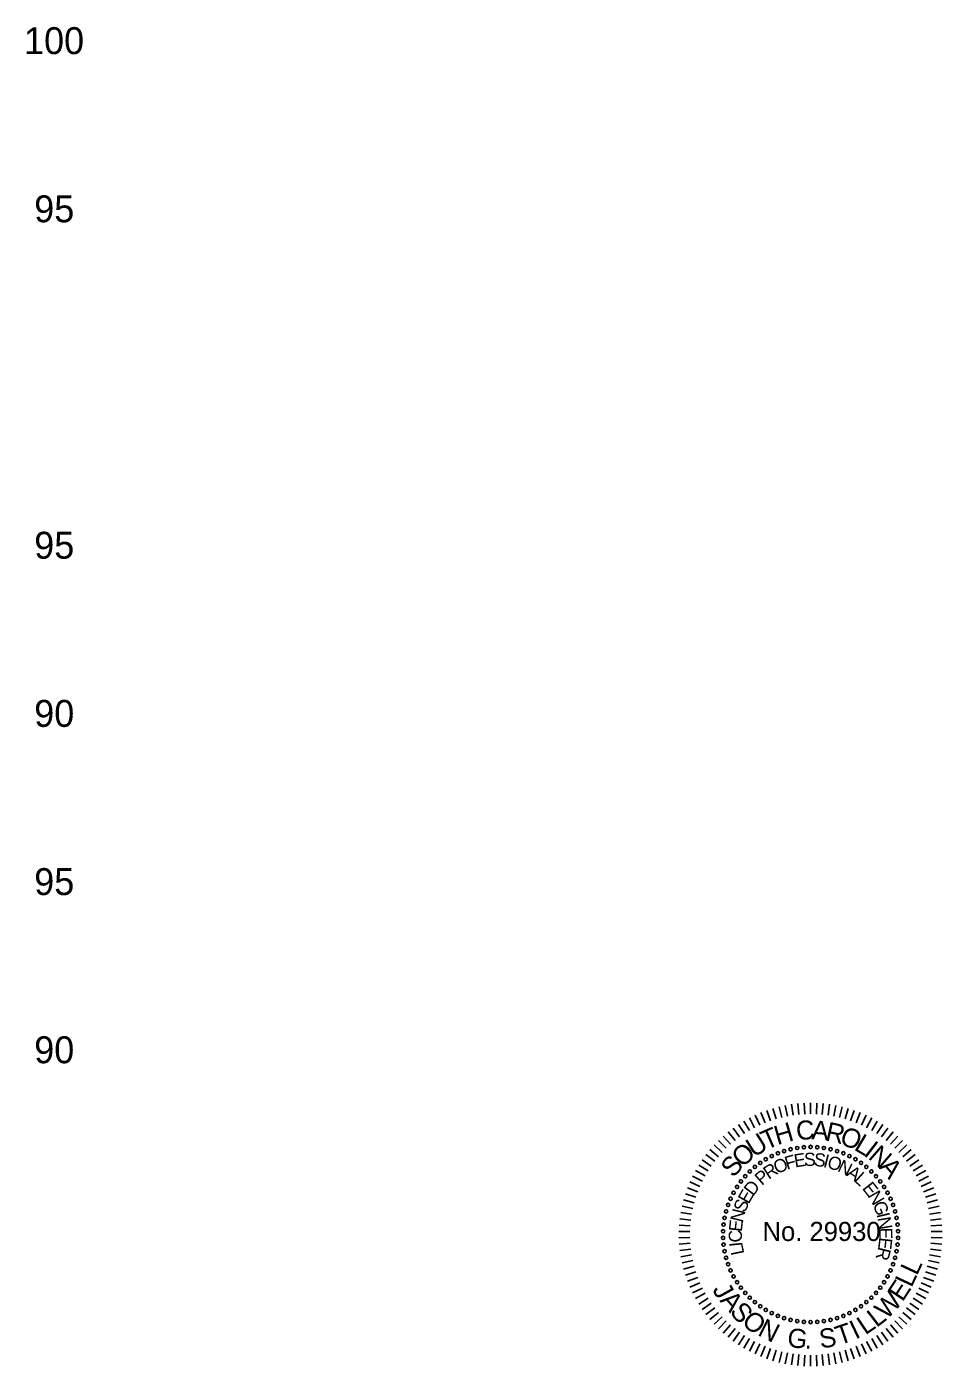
# Model space of a CAD drawing. Extents: x 1001 to 1184, y 1001 to 1102.
# Drawn here: x 1156.7 to 1183.91, y 1000.99 to 1040.81 of the extents above; entities that cross this region are included whole.
import ezdxf

# ---------------------------------------------------------------- set-up
doc = ezdxf.new("R2010")
doc.units = 0
for name, color, linetype in [('RD_HC_Cl', 7, 'Continuous'), ('RD_TX_PEShield', 7, 'Continuous'), ('RD_XS_TX_Elev_EX', 7, 'Continuous')]:
    doc.layers.add(name, color=color, linetype=linetype)

# ---------------------------------------------------------------- blocks, each defined once
blk = doc.blocks.new('STILLWELL')
at = {"layer": 'RD_TX_PEShield'}
for p, q in [((-11.93, 32.91), (-13.02, 35.99)), ((-10.28, 33.44), (-11.22, 36.57)), ((-8.61, 33.9), (-9.39, 37.07)), ((-6.92, 34.27), (-7.55, 37.48)), ((-5.21, 34.57), (-5.68, 37.8)), ((-3.49, 34.77), (-3.81, 38.03)), ((-1.76, 34.9), (-1.92, 38.16)), ((-0.03, 34.94), (-0.03, 38.21)), ((1.71, 34.9), (1.86, 38.16)), ((3.43, 34.77), (3.75, 38.03)), ((5.15, 34.57), (5.63, 37.8)), ((6.86, 34.27), (7.49, 37.48)), ((8.56, 33.9), (9.34, 37.07)), ((10.23, 33.44), (11.16, 36.57)), ((11.88, 32.91), (12.96, 35.99)), ((-18.21, 29.99), (-19.87, 32.81)), ((-16.7, 30.83), (-18.22, 33.73)), ((-15.14, 31.6), (-16.52, 34.56)), ((-13.55, 32.29), (-14.79, 35.32)), ((13.5, 32.29), (14.73, 35.32)), ((15.09, 31.6), (16.46, 34.56)), ((16.64, 30.83), (18.16, 33.73)), ((18.16, 29.99), (19.81, 32.81)), ((-23.81, 25.92), (-25.98, 28.37)), ((-22.49, 27.04), (-24.53, 29.59)), ((-21.11, 28.09), (-23.03, 30.73)), ((-19.68, 29.08), (-21.48, 31.81)), ((19.63, 29.08), (21.42, 31.81)), ((21.06, 28.09), (22.98, 30.73)), ((22.43, 27.04), (24.48, 29.59)), ((23.76, 25.92), (25.92, 28.37)), ((-27.44, 22.2), (-29.94, 24.31)), ((-26.29, 23.5), (-28.69, 25.72)), ((-25.08, 24.74), (-27.37, 27.08)), ((25.03, 24.74), (27.31, 27.08)), ((26.24, 23.5), (28.63, 25.72)), ((27.39, 22.2), (29.88, 24.31)), ((-29.55, 19.45), (-32.24, 21.3)), ((-28.53, 20.85), (-31.12, 22.83)), ((28.47, 20.85), (31.07, 22.83)), ((29.49, 19.45), (32.18, 21.3)), ((-32.18, 14.97), (-35.11, 16.42)), ((-31.38, 16.5), (-34.23, 18.09)), ((-30.5, 18), (-33.27, 19.72)), ((30.44, 18), (33.22, 19.72)), ((31.32, 16.5), (34.18, 18.09)), ((32.13, 14.97), (35.06, 16.42)), ((-33.57, 11.79), (-36.62, 12.95)), ((-32.91, 13.4), (-35.91, 14.7)), ((32.86, 13.4), (35.85, 14.7)), ((33.51, 11.79), (36.57, 12.95)), ((-34.64, 8.5), (-37.79, 9.35)), ((-34.14, 10.16), (-37.25, 11.17)), ((34.09, 10.16), (37.19, 11.17)), ((34.58, 8.5), (37.73, 9.35)), ((-35.39, 5.11), (-38.61, 5.66)), ((-35.05, 6.81), (-38.24, 7.52)), ((35, 6.81), (38.19, 7.52)), ((35.33, 5.11), (38.55, 5.66)), ((-35.89, -0.06), (-39.15, 0.02)), ((-35.8, 1.67), (-39.06, 1.91)), ((-35.64, 3.4), (-38.88, 3.79)), ((35.58, 3.4), (38.82, 3.79)), ((35.75, 1.67), (39.01, 1.91)), ((35.83, -0.06), (39.1, 0.02)), ((-35.89, -1.79), (-39.15, -1.87)), ((-35.8, -3.53), (-39.06, -3.76)), ((35.75, -3.53), (39.01, -3.76)), ((35.83, -1.79), (39.1, -1.87)), ((-35.64, -5.25), (-38.88, -5.65)), ((-35.39, -6.97), (-38.61, -7.52)), ((35.33, -6.97), (38.55, -7.52)), ((35.58, -5.25), (38.82, -5.65)), ((-35.05, -8.67), (-38.24, -9.37)), ((-34.64, -10.35), (-37.79, -11.21)), ((34.58, -10.35), (37.73, -11.21)), ((35, -8.67), (38.19, -9.37)), ((-34.14, -12.01), (-37.25, -13.02)), ((-33.57, -13.65), (-36.62, -14.81)), ((-32.91, -15.25), (-35.91, -16.56)), ((32.86, -15.25), (35.85, -16.56)), ((33.51, -13.65), (36.57, -14.81)), ((34.09, -12.01), (37.19, -13.02)), ((-32.18, -16.83), (-35.11, -18.27)), ((-31.38, -18.36), (-34.23, -19.95)), ((-30.5, -19.85), (-33.27, -21.58)), ((30.44, -19.85), (33.22, -21.58)), ((31.32, -18.36), (34.18, -19.95)), ((32.13, -16.83), (35.06, -18.27)), ((-29.55, -21.3), (-32.24, -23.16)), ((-28.53, -22.71), (-31.12, -24.69)), ((28.47, -22.71), (31.07, -24.69)), ((29.49, -21.3), (32.18, -23.16)), ((-27.44, -24.06), (-29.94, -26.16)), ((-26.29, -25.36), (-28.69, -27.58)), ((-25.08, -26.6), (-27.37, -28.93)), ((-23.81, -27.78), (-25.98, -30.22)), ((23.76, -27.78), (25.92, -30.22)), ((25.03, -26.6), (27.31, -28.93)), ((26.24, -25.36), (28.63, -27.58)), ((27.39, -24.06), (29.88, -26.16)), ((-22.49, -28.89), (-24.53, -31.44)), ((-21.11, -29.95), (-23.03, -32.59)), ((-19.68, -30.93), (-21.48, -33.66)), ((-18.21, -31.85), (-19.87, -34.66)), ((18.16, -31.85), (19.81, -34.66)), ((19.63, -30.93), (21.42, -33.66)), ((21.06, -29.95), (22.98, -32.59)), ((22.43, -28.89), (24.48, -31.44)), ((-16.7, -32.69), (-18.22, -35.58)), ((-15.14, -33.46), (-16.52, -36.42)), ((-13.55, -34.15), (-14.79, -37.18)), ((-11.93, -34.76), (-13.02, -37.85)), ((-10.28, -35.3), (-11.22, -38.43)), ((-8.61, -35.76), (-9.39, -38.93)), ((8.56, -35.76), (9.34, -38.93)), ((10.23, -35.3), (11.16, -38.43)), ((11.88, -34.76), (12.96, -37.85)), ((13.5, -34.15), (14.73, -37.18)), ((15.09, -33.46), (16.46, -36.42)), ((16.64, -32.69), (18.16, -35.58)), ((-6.92, -36.13), (-7.55, -39.34)), ((-5.21, -36.42), (-5.68, -39.65)), ((-3.49, -36.63), (-3.81, -39.88)), ((-1.76, -36.76), (-1.92, -40.02)), ((-0.03, -36.8), (-0.03, -40.06)), ((1.71, -36.76), (1.86, -40.02)), ((3.43, -36.63), (3.75, -39.88)), ((5.15, -36.42), (5.63, -39.65)), ((6.86, -36.13), (7.49, -39.34))]:
    blk.add_line(p, q, dxfattribs=at)
for centre in [(-7.89, 23.9), (-5.96, 24.43), (-4, 24.81), (-2.02, 25.04), (-0.03, 25.12), (1.97, 25.04), (3.95, 24.81), (5.91, 24.43), (7.83, 23.9), (-15.01, 20.38), (-13.34, 21.46), (-11.59, 22.41), (-9.76, 23.23), (9.71, 23.23), (11.53, 22.41), (13.28, 21.46), (14.96, 20.38), (-19.47, 16.4), (-18.09, 17.84), (-16.6, 19.17), (16.54, 19.17), (18.03, 17.84), (19.42, 16.4), (-22.91, 11.51), (-21.89, 13.23), (-20.74, 14.86), (20.69, 14.86), (21.83, 13.23), (22.85, 11.51), (-24.54, 7.88), (-23.79, 9.73), (23.74, 9.73), (24.48, 7.88), (-25.6, 4.03), (-25.14, 5.97), (25.09, 5.97), (25.54, 4.03), (-26.05, 0.07), (-25.9, 2.06), (25.85, 2.06), (26, 0.07), (-26.05, -1.93), (-25.9, -3.92), (25.85, -3.92), (26, -1.93), (-25.6, -5.89), (-25.14, -7.83), (25.09, -7.83), (25.54, -5.89), (-24.54, -9.73), (-23.79, -11.58), (23.74, -11.58), (24.48, -9.73), (-22.91, -13.37), (-21.89, -15.09), (21.83, -15.09), (22.85, -13.37), (-20.74, -16.72), (-19.47, -18.26), (-18.09, -19.69), (18.03, -19.69), (19.42, -18.26), (20.69, -16.72), (-16.6, -21.02), (-15.01, -22.23), (-13.34, -23.32), (-11.59, -24.27), (11.53, -24.27), (13.28, -23.32), (14.96, -22.23), (16.54, -21.02), (-9.76, -25.09), (-7.89, -25.76), (-5.96, -26.29), (-4, -26.67), (-2.02, -26.9), (-0.03, -26.97), (1.97, -26.9), (3.95, -26.67), (5.91, -26.29), (7.83, -25.76), (9.71, -25.09)]:
    blk.add_circle(centre, 0.49, dxfattribs=at)
for s, height, rotation, p in [('H', 5.68, 16.1357, (-9.92, 25.63)), ('C', 5.68, 4.076, (-4.15, 27.11)), ('A', 5.68, 355.3651, (0.14, 27.41)), ('R', 5.68, 347.3188, (4.1, 27.11)), ('U', 5.68, 32.2152, (-16.89, 21.85)), ('T', 5.68, 23.5044, (-13.24, 24.14)), ('O', 5.68, 338.6079, (8.3, 26.16)), ('L', 5.68, 329.226, (12.61, 24.44)), ('O', 5.68, 41.5972, (-20.38, 18.79)), ('I', 5.68, 322.5218, (15.48, 22.79)), ('N', 5.68, 319.1729, (16.84, 21.84)), ('S', 5.68, 49.6435, (-22.94, 15.75)), ('R', 3.92, 33.3057, (-12.46, 15.32)), ('O', 3.92, 24.9735, (-9.98, 16.95)), ('F', 3.92, 15.9995, (-7.07, 18.28)), ('E', 3.92, 8.9511, (-4.65, 19)), ('S', 3.92, 1.2546, (-1.94, 19.44)), ('S', 3.92, 353.558, (0.8, 19.51)), ('I', 3.92, 345.8615, (3.53, 19.22)), ('O', 3.92, 342.6583, (4.65, 18.99)), ('N', 3.92, 333.6842, (7.7, 18.01)), ('A', 5.68, 310.4621, (20.09, 19.02)), ('P', 3.92, 41.0022, (-14.52, 13.51)), ('A', 3.92, 325.3521, (10.36, 16.69)), ('L', 3.92, 317.6555, (12.63, 15.14)), ('E', 3.92, 60.2341, (-18.47, 7.93)), ('D', 3.92, 52.5376, (-17.12, 10.32)), ('E', 3.92, 308.0396, (15.14, 12.8)), ('N', 3.92, 300.343, (16.84, 10.65)), ('S', 3.92, 67.9307, (-19.49, 5.38)), ('G', 3.92, 292.0109, (18.34, 8.08)), ('N', 3.92, 76.2628, (-20.2, 2.49)), ('I', 3.92, 283.0368, (19.52, 5.11)), ('N', 3.92, 279.8336, (19.83, 4.01)), ('C', 3.92, 92.2915, (-20.36, -3.21)), ('E', 3.92, 83.9594, (-20.47, -0.24)), ('E', 3.92, 271.5014, (20.33, 1.08)), ('I', 3.92, 95.4947, (-20.2, -4.35)), ('L', 3.92, 101.9075, (-19.69, -6.58)), ('E', 3.92, 263.8049, (20.42, -1.67)), ('R', 3.92, 256.1083, (20.13, -4.4)), ('L', 5.68, 65.098, (31.58, -13.34)), ('J', 5.68, 299.033, (-29.35, -17.26)), ('E', 5.68, 56.4327, (27.3, -21.12)), ('L', 5.68, 65.098, (29.98, -16.89)), ('A', 5.68, 310.5887, (-27.19, -20.61)), ('W', 5.68, 47.0518, (22.62, -26.41)), ('S', 5.68, 310.5887, (-24.3, -23.99)), ('L', 5.68, 37.6708, (19.57, -28.72)), ('O', 5.68, 321.0072, (-20.82, -27.39)), ('N', 5.68, 333.4326, (-16.05, -30.75)), ('T', 5.68, 18.9019, (8.5, -33.88)), ('I', 5.68, 25.3991, (13.3, -32.17)), ('L', 5.68, 34.0644, (16.21, -30.92)), ('G', 5.68, 352.2045, (-7.22, -34.2)), ('S', 5.68, 8.0826, (2.93, -34.79)), ('.', 5.68, 0.8698, (-1.8, -34.9))]:
    blk.add_text(s, height=height, rotation=rotation, dxfattribs=at).set_placement(p)
blk.add_text('No. 29930', height=5.685, dxfattribs=at).set_placement((-14.3, -2.84))

msp = doc.modelspace()

# ---------------------------------------------------------------- block references
at = {"layer": 'RD_HC_Cl', "xscale": 0.1, "yscale": 0.10000000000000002}
msp.add_blockref('STILLWELL', (1179.999, 1005), dxfattribs=at)

# ---------------------------------------------------------------- texts
at = {"layer": 'RD_XS_TX_Elev_EX'}
for s, p in [('100', (1156.616, 1040)), ('95', (1156.919, 1035)), ('95', (1156.919, 1025)), ('90', (1156.919, 1020)), ('95', (1156.919, 1015)), ('90', (1156.919, 1010))]:
    msp.add_text(s, height=0.8, dxfattribs=at).set_placement(p)

doc.saveas('drawing.dxf')
